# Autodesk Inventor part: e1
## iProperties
Created: 2002-02
Part Number: e1
Document SubType Name: ﾓﾃﾞﾘﾝｸﾞ
Designer: Administrator
Control State: 0
Master: False
Checked Out: False
Shininess: 64.0
Length Units: 11269
Angle Units: 11279
Time Units: 11290
Mass Units: 11284
Length Display Precision: 2
Angle Display Precision: 1
Density: 0.0
Volumn: 0.0
Area: 0.0
PropertySet Name: Model Information
Author: Administrator
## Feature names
1. 押し出し1 [Extrusion]
2. 押し出し2 [Extrusion]
3. 面取り1 [Chamfer]
4. 押し出し3 [Extrusion]
